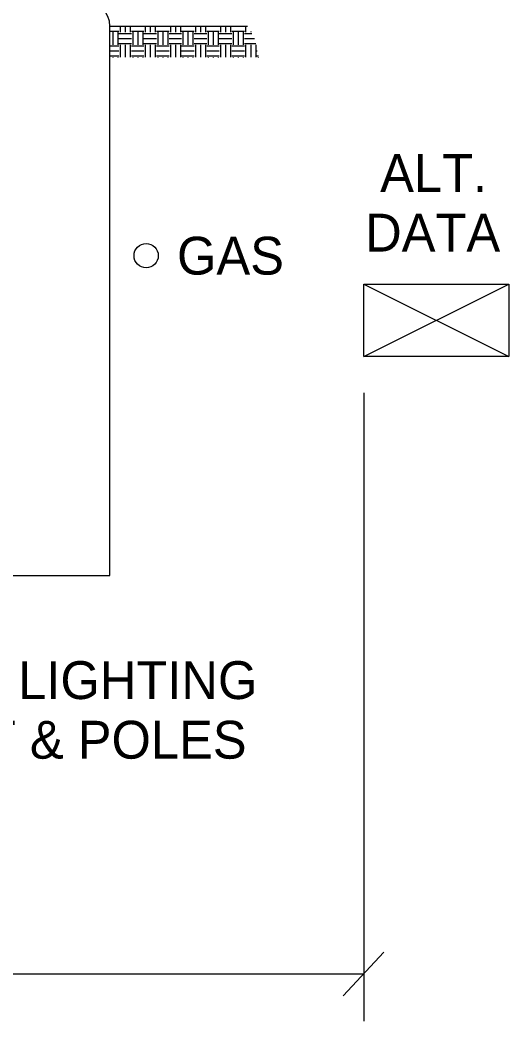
# Model space of a CAD drawing. Extents: x 27101070.6 to 27101150.6, y 1158854.7 to 1158902.9.
# Drawn here: x 27101135.94 to 27101142.68, y 1158875.06 to 1158888.86 of the extents above; entities that cross this region are included whole.
import ezdxf

# ---------------------------------------------------------------- set-up
doc = ezdxf.new("R2010")
doc.units = 0
for name, color, linetype in [('G-ANNO-TEXT', 7, 'Continuous'), ('G-DETL-LINE', 7, 'Continuous'), ('G-DETL-OTLN', 7, 'Continuous'), ('G-DETL-PATT', 7, 'Continuous')]:
    doc.layers.add(name, color=color, linetype=linetype)

msp = doc.modelspace()

# ---------------------------------------------------------------- linework, layer by layer
at = {"layer": 'G-ANNO-TEXT'}
for p, q in [((27101140.676, 1158883.719), (27101140.676, 1158875.058)), ((27101140.389, 1158875.407), (27101140.952, 1158876.008)), ((27101125.676, 1158875.707), (27101140.676, 1158875.707))]:
    msp.add_line(p, q, dxfattribs=at)
at = {"layer": 'G-DETL-LINE'}
msp.add_line((27101137.174, 1158888.778), (27101139.07, 1158888.778), dxfattribs=at)
at = {"layer": 'G-DETL-OTLN'}
for p, q in [((27101137.174, 1158887.18), (27101137.174, 1158888.778)), ((27101137.174, 1158881.203), (27101137.174, 1158887.18)), ((27101140.676, 1158885.22), (27101142.676, 1158885.22)), ((27101140.676, 1158884.22), (27101140.676, 1158885.22)), ((27101142.676, 1158885.22), (27101142.676, 1158884.22)), ((27101142.676, 1158884.22), (27101140.676, 1158884.22)), ((27101135.174, 1158881.203), (27101137.174, 1158881.203))]:
    msp.add_line(p, q, dxfattribs=at)
msp.add_circle((27101137.674, 1158885.612), 0.167, dxfattribs=at)
msp.add_arc((27101136.833, 1158888.778), 0.341, 360, 90, dxfattribs=at)
at = {"layer": 'G-DETL-PATT'}
for p, q in [((27101137.174, 1158888.71), (27101137.298, 1158888.71)), ((27101137.213, 1158888.693), (27101137.213, 1158888.52)), ((27101137.282, 1158888.693), (27101137.282, 1158888.52)), ((27101137.298, 1158888.677), (27101137.471, 1158888.677)), ((27101137.315, 1158888.778), (27101137.315, 1158888.693)), ((27101137.385, 1158888.778), (27101137.385, 1158888.693)), ((27101137.454, 1158888.778), (27101137.454, 1158888.693)), ((27101137.471, 1158888.71), (27101137.644, 1158888.71)), ((27101137.49, 1158888.693), (27101137.49, 1158888.52)), ((27101137.559, 1158888.693), (27101137.559, 1158888.52)), ((27101137.628, 1158888.693), (27101137.628, 1158888.52)), ((27101137.644, 1158888.677), (27101137.817, 1158888.677)), ((27101137.661, 1158888.778), (27101137.661, 1158888.693)), ((27101137.731, 1158888.778), (27101137.731, 1158888.693)), ((27101137.8, 1158888.778), (27101137.8, 1158888.693)), ((27101137.817, 1158888.71), (27101137.99, 1158888.71)), ((27101137.836, 1158888.693), (27101137.836, 1158888.52)), ((27101137.905, 1158888.693), (27101137.905, 1158888.52)), ((27101137.974, 1158888.693), (27101137.974, 1158888.52)), ((27101137.99, 1158888.677), (27101138.163, 1158888.677)), ((27101138.008, 1158888.778), (27101138.008, 1158888.693)), ((27101138.077, 1158888.778), (27101138.077, 1158888.693)), ((27101138.146, 1158888.778), (27101138.146, 1158888.693)), ((27101138.163, 1158888.71), (27101138.336, 1158888.71)), ((27101138.182, 1158888.693), (27101138.182, 1158888.52)), ((27101138.251, 1158888.693), (27101138.251, 1158888.52)), ((27101138.32, 1158888.693), (27101138.32, 1158888.52)), ((27101138.336, 1158888.677), (27101138.509, 1158888.677)), ((27101138.354, 1158888.778), (27101138.354, 1158888.693)), ((27101138.423, 1158888.778), (27101138.423, 1158888.693)), ((27101138.492, 1158888.778), (27101138.492, 1158888.693)), ((27101138.509, 1158888.71), (27101138.683, 1158888.71)), ((27101138.528, 1158888.693), (27101138.528, 1158888.52)), ((27101138.597, 1158888.693), (27101138.597, 1158888.52)), ((27101138.666, 1158888.693), (27101138.666, 1158888.52)), ((27101138.683, 1158888.677), (27101138.856, 1158888.677)), ((27101138.7, 1158888.778), (27101138.7, 1158888.693)), ((27101138.769, 1158888.778), (27101138.769, 1158888.693)), ((27101138.838, 1158888.778), (27101138.838, 1158888.693)), ((27101138.856, 1158888.71), (27101139.029, 1158888.71)), ((27101138.874, 1158888.693), (27101138.874, 1158888.52)), ((27101138.943, 1158888.693), (27101138.943, 1158888.52)), ((27101139.013, 1158888.693), (27101139.013, 1158888.52)), ((27101139.029, 1158888.677), (27101139.132, 1158888.677)), ((27101139.046, 1158888.778), (27101139.046, 1158888.693)), ((27101139.115, 1158888.704), (27101139.115, 1158888.693)), ((27101137.298, 1158888.608), (27101137.471, 1158888.608)), ((27101137.298, 1158888.539), (27101137.471, 1158888.539)), ((27101137.315, 1158888.521), (27101137.315, 1158888.348)), ((27101137.385, 1158888.521), (27101137.385, 1158888.348)), ((27101137.454, 1158888.521), (27101137.454, 1158888.348)), ((27101137.644, 1158888.608), (27101137.817, 1158888.608)), ((27101137.644, 1158888.539), (27101137.817, 1158888.539)), ((27101137.661, 1158888.521), (27101137.661, 1158888.348)), ((27101137.731, 1158888.521), (27101137.731, 1158888.348)), ((27101137.8, 1158888.521), (27101137.8, 1158888.348)), ((27101137.99, 1158888.608), (27101138.163, 1158888.608)), ((27101137.99, 1158888.539), (27101138.163, 1158888.539)), ((27101138.008, 1158888.521), (27101138.008, 1158888.348)), ((27101138.077, 1158888.521), (27101138.077, 1158888.348)), ((27101138.146, 1158888.521), (27101138.146, 1158888.348)), ((27101138.336, 1158888.608), (27101138.509, 1158888.608)), ((27101138.336, 1158888.539), (27101138.509, 1158888.539)), ((27101138.354, 1158888.521), (27101138.354, 1158888.348)), ((27101138.423, 1158888.521), (27101138.423, 1158888.348)), ((27101138.492, 1158888.521), (27101138.492, 1158888.348)), ((27101138.683, 1158888.608), (27101138.856, 1158888.608)), ((27101138.683, 1158888.539), (27101138.856, 1158888.539)), ((27101138.7, 1158888.521), (27101138.7, 1158888.348)), ((27101138.769, 1158888.521), (27101138.769, 1158888.348)), ((27101138.838, 1158888.521), (27101138.838, 1158888.348)), ((27101139.029, 1158888.608), (27101139.169, 1158888.608)), ((27101139.029, 1158888.539), (27101139.184, 1158888.539)), ((27101139.046, 1158888.521), (27101139.046, 1158888.348)), ((27101139.115, 1158888.521), (27101139.115, 1158888.348)), ((27101139.184, 1158888.521), (27101139.184, 1158888.348)), ((27101137.174, 1158888.504), (27101137.298, 1158888.504)), ((27101137.174, 1158888.435), (27101137.298, 1158888.435)), ((27101137.471, 1158888.504), (27101137.644, 1158888.504)), ((27101137.471, 1158888.435), (27101137.644, 1158888.435)), ((27101137.817, 1158888.504), (27101137.99, 1158888.504)), ((27101137.817, 1158888.435), (27101137.99, 1158888.435)), ((27101138.163, 1158888.504), (27101138.336, 1158888.504)), ((27101138.163, 1158888.435), (27101138.336, 1158888.435)), ((27101138.509, 1158888.504), (27101138.683, 1158888.504)), ((27101138.509, 1158888.435), (27101138.683, 1158888.435)), ((27101138.856, 1158888.504), (27101139.029, 1158888.504)), ((27101138.856, 1158888.435), (27101139.029, 1158888.435)), ((27101139.202, 1158888.435), (27101139.206, 1158888.435)), ((27101137.174, 1158888.366), (27101137.298, 1158888.366)), ((27101137.213, 1158888.348), (27101137.213, 1158888.347)), ((27101137.282, 1158888.348), (27101137.282, 1158888.347)), ((27101137.471, 1158888.366), (27101137.644, 1158888.366)), ((27101137.49, 1158888.348), (27101137.49, 1158888.347)), ((27101137.559, 1158888.348), (27101137.559, 1158888.347)), ((27101137.628, 1158888.348), (27101137.628, 1158888.347)), ((27101137.817, 1158888.366), (27101137.99, 1158888.366)), ((27101137.836, 1158888.348), (27101137.836, 1158888.347)), ((27101137.905, 1158888.348), (27101137.905, 1158888.347)), ((27101137.974, 1158888.348), (27101137.974, 1158888.347)), ((27101138.163, 1158888.366), (27101138.336, 1158888.366)), ((27101138.182, 1158888.348), (27101138.182, 1158888.347)), ((27101138.251, 1158888.348), (27101138.251, 1158888.347)), ((27101138.32, 1158888.348), (27101138.32, 1158888.347)), ((27101138.509, 1158888.366), (27101138.683, 1158888.366)), ((27101138.528, 1158888.348), (27101138.528, 1158888.347)), ((27101138.597, 1158888.348), (27101138.597, 1158888.347)), ((27101138.666, 1158888.348), (27101138.666, 1158888.347)), ((27101138.856, 1158888.366), (27101139.029, 1158888.366)), ((27101138.874, 1158888.348), (27101138.874, 1158888.347)), ((27101138.943, 1158888.348), (27101138.943, 1158888.347)), ((27101139.013, 1158888.348), (27101139.013, 1158888.347)), ((27101139.202, 1158888.366), (27101139.221, 1158888.366)), ((27101139.22, 1158888.348), (27101139.22, 1158888.347)), ((27101140.676, 1158884.22), (27101142.676, 1158885.22)), ((27101140.676, 1158885.22), (27101142.676, 1158884.22))]:
    msp.add_line(p, q, dxfattribs=at)

# ---------------------------------------------------------------- texts
at = {"layer": 'G-ANNO-TEXT'}
for s, p in [('ALT.', (27101140.9, 1158886.491)), ('DATA', (27101140.693, 1158885.669)), ('GAS', (27101138.1, 1158885.351)), ('POWER & LIGHTING', (27101132.42, 1158879.498)), ('CONDUIT & POLES', (27101132.698, 1158878.676))]:
    msp.add_text(s, height=0.522, dxfattribs=at).set_placement(p)

doc.saveas('drawing.dxf')
